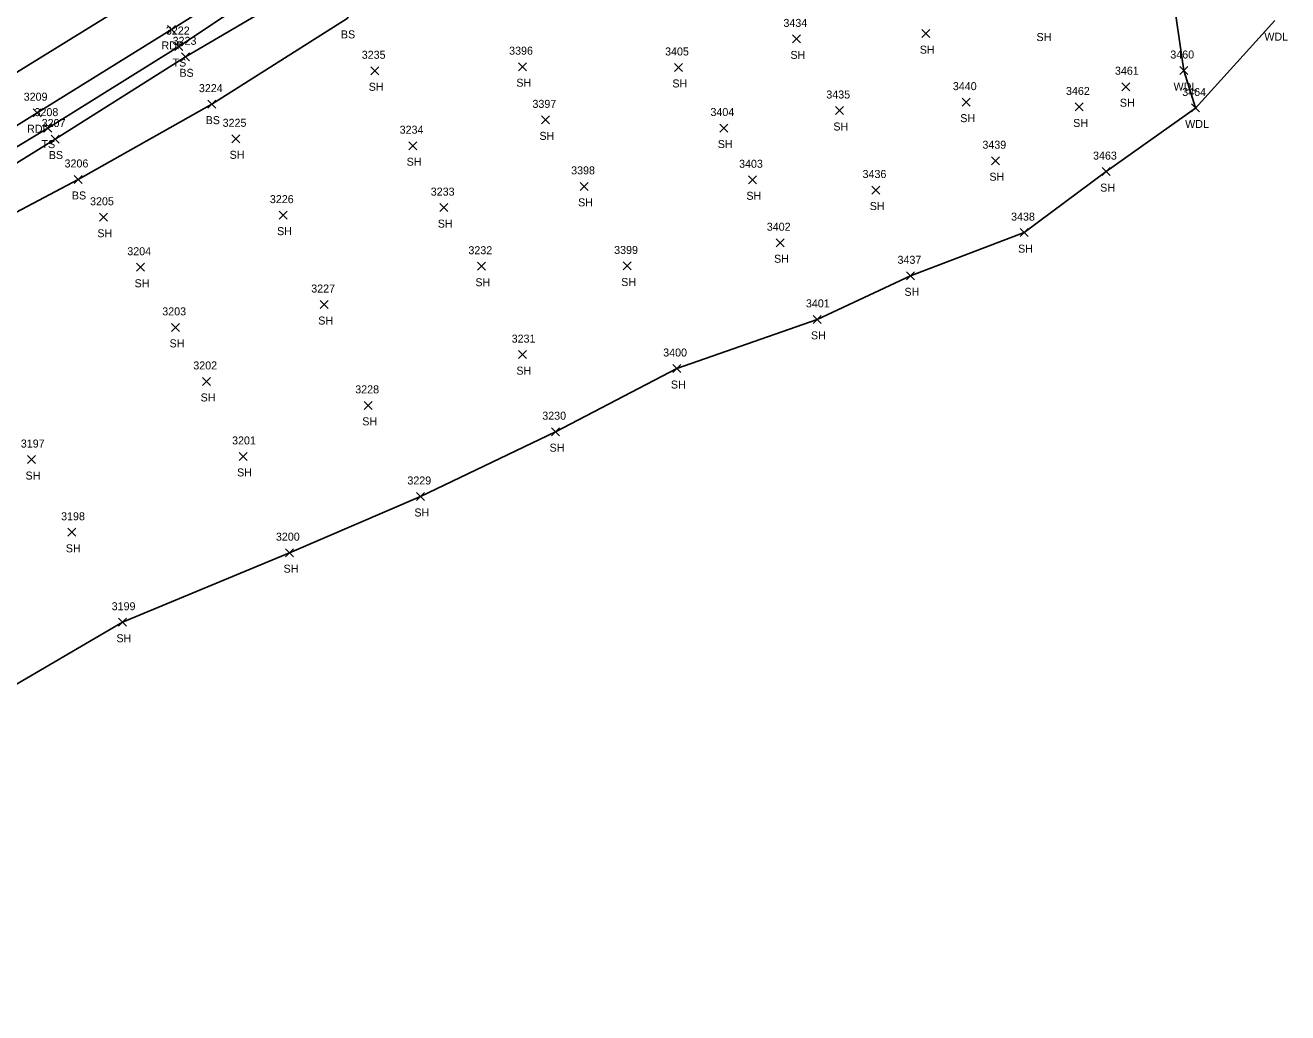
# Model space of a CAD drawing. Extents: x 1443590 to 1445966, y 578314 to 580556.
# Drawn here: x 1443948 to 1444263.5, y 578545.9 to 578792.7 of the extents above; entities that cross this region are included whole.
import ezdxf

# ---------------------------------------------------------------- set-up
doc = ezdxf.new("R2010")
doc.units = 0
for name, color, linetype in [('L_A', 7, 'Continuous'), ('L_I', 7, 'Continuous'), ('L_TIC', 7, 'Continuous'), ('LAWA', 7, 'Continuous'), ('LELB', 7, 'Continuous'), ('LSOGP', 7, 'Continuous'), ('P_A', 7, 'Continuous'), ('P_I', 7, 'Continuous'), ('P_TIC', 7, 'Continuous'), ('PET', 7, 'Continuous'), ('PRC', 7, 'Continuous')]:
    doc.layers.add(name, color=color, linetype=linetype)

msp = doc.modelspace()

# ---------------------------------------------------------------- linework, layer by layer
at = {"layer": 'L_TIC'}
for points in [[(1444139.75, 578788.3), (1444141.75, 578790.3)], [(1444141.75, 578788.3), (1444139.75, 578790.3)], [(1444172.09, 578789.62), (1444174.09, 578791.62)], [(1444174.09, 578789.62), (1444172.09, 578791.62)], [(1443985.4, 578786.39), (1443987.4, 578788.39)], [(1443987.4, 578786.39), (1443985.4, 578788.39)], [(1443987.08, 578783.83), (1443989.08, 578785.83)], [(1443989.08, 578783.83), (1443987.08, 578785.83)], [(1444071.24, 578781.36), (1444073.24, 578783.36)], [(1444073.24, 578781.36), (1444071.24, 578783.36)], [(1444110.25, 578781.17), (1444112.25, 578783.17)], [(1444112.25, 578781.17), (1444110.25, 578783.17)], [(1444034.35, 578780.34), (1444036.35, 578782.34)], [(1444036.35, 578780.34), (1444034.35, 578782.34)], [(1444236.58, 578780.4), (1444238.58, 578782.4)], [(1444238.58, 578780.4), (1444236.58, 578782.4)], [(1444222.09, 578776.35), (1444224.09, 578778.35)], [(1444224.09, 578776.35), (1444222.09, 578778.35)], [(1443993.65, 578772), (1443995.65, 578774)], [(1443995.65, 578772), (1443993.65, 578774)], [(1444182.19, 578772.5), (1444184.19, 578774.5)], [(1444184.19, 578772.5), (1444182.19, 578774.5)], [(1444210.42, 578771.3), (1444212.42, 578773.3)], [(1444212.42, 578771.3), (1444210.42, 578773.3)], [(1444077.02, 578768.07), (1444079.02, 578770.07)], [(1444079.02, 578768.07), (1444077.02, 578770.07)], [(1444150.47, 578770.41), (1444152.47, 578772.41)], [(1444152.47, 578770.41), (1444150.47, 578772.41)], [(1444239.48, 578771.04), (1444241.48, 578773.04)], [(1444241.48, 578771.04), (1444239.48, 578773.04)], [(1443952.64, 578766.01), (1443954.64, 578768.01)], [(1443954.64, 578766.01), (1443952.64, 578768.01)], [(1444121.59, 578766.03), (1444123.59, 578768.03)], [(1444123.59, 578766.03), (1444121.59, 578768.03)], [(1443954.43, 578763.28), (1443956.43, 578765.28)], [(1443956.43, 578763.28), (1443954.43, 578765.28)], [(1443999.58, 578763.34), (1444001.58, 578765.34)], [(1444001.58, 578763.34), (1443999.58, 578765.34)], [(1444043.83, 578761.61), (1444045.83, 578763.61)], [(1444045.83, 578761.61), (1444043.83, 578763.61)], [(1444189.49, 578757.86), (1444191.49, 578759.86)], [(1444191.49, 578757.86), (1444189.49, 578759.86)], [(1443960.2, 578753.18), (1443962.2, 578755.18)], [(1443962.2, 578753.18), (1443960.2, 578755.18)], [(1444128.74, 578753.1), (1444130.74, 578755.1)], [(1444130.74, 578753.1), (1444128.74, 578755.1)], [(1444217.18, 578755.14), (1444219.18, 578757.14)], [(1444219.18, 578755.14), (1444217.18, 578757.14)], [(1444086.69, 578751.45), (1444088.69, 578753.45)], [(1444088.69, 578751.45), (1444086.69, 578753.45)], [(1444159.59, 578750.54), (1444161.59, 578752.54)], [(1444161.59, 578750.54), (1444159.59, 578752.54)], [(1444051.6, 578746.14), (1444053.6, 578748.14)], [(1444053.6, 578746.14), (1444051.6, 578748.14)], [(1443966.52, 578743.73), (1443968.52, 578745.73)], [(1443968.52, 578743.73), (1443966.52, 578745.73)], [(1444011.44, 578744.26), (1444013.44, 578746.26)], [(1444013.44, 578744.26), (1444011.44, 578746.26)], [(1444196.65, 578739.89), (1444198.65, 578741.89)], [(1444198.65, 578739.89), (1444196.65, 578741.89)], [(1444135.67, 578737.36), (1444137.67, 578739.36)], [(1444137.67, 578737.36), (1444135.67, 578739.36)], [(1443975.83, 578731.24), (1443977.83, 578733.24)], [(1443977.83, 578731.24), (1443975.83, 578733.24)], [(1444061.01, 578731.49), (1444063.01, 578733.49)], [(1444063.01, 578731.49), (1444061.01, 578733.49)], [(1444097.45, 578731.56), (1444099.45, 578733.56)], [(1444099.45, 578731.56), (1444097.45, 578733.56)], [(1444168.26, 578729.1), (1444170.26, 578731.1)], [(1444170.26, 578729.1), (1444168.26, 578731.1)], [(1444021.73, 578721.92), (1444023.73, 578723.92)], [(1444023.73, 578721.92), (1444021.73, 578723.92)], [(1444144.89, 578718.21), (1444146.89, 578720.21)], [(1444146.89, 578718.21), (1444144.89, 578720.21)], [(1443984.57, 578716.21), (1443986.57, 578718.21)], [(1443986.57, 578716.21), (1443984.57, 578718.21)], [(1444071.25, 578709.4), (1444073.25, 578711.4)], [(1444073.25, 578709.4), (1444071.25, 578711.4)], [(1444109.87, 578705.93), (1444111.87, 578707.93)], [(1444111.87, 578705.93), (1444109.87, 578707.93)], [(1443992.33, 578702.7), (1443994.33, 578704.7)], [(1443994.33, 578702.7), (1443992.33, 578704.7)], [(1444032.73, 578696.72), (1444034.73, 578698.72)], [(1444034.73, 578696.72), (1444032.73, 578698.72)], [(1444079.56, 578690.14), (1444081.56, 578692.14)], [(1444081.56, 578690.14), (1444079.56, 578692.14)], [(1443948.58, 578683.18), (1443950.58, 578685.18)], [(1443950.58, 578683.18), (1443948.58, 578685.18)], [(1444001.46, 578683.96), (1444003.46, 578685.96)], [(1444003.46, 578683.96), (1444001.46, 578685.96)], [(1444045.76, 578673.95), (1444047.76, 578675.95)], [(1444047.76, 578673.95), (1444045.76, 578675.95)], [(1443958.64, 578665), (1443960.64, 578667)], [(1443960.64, 578665), (1443958.64, 578667)], [(1444013.06, 578659.91), (1444015.06, 578661.91)], [(1444015.06, 578659.91), (1444013.06, 578661.91)], [(1443971.29, 578642.52), (1443973.29, 578644.52)], [(1443973.29, 578642.52), (1443971.29, 578644.52)]]:
    msp.add_lwpolyline(points, dxfattribs=at)
at = {"layer": 'LAWA'}
msp.add_lwpolyline([(1444048.1, 578821.32), (1444049.15, 578815.65), (1444053.76, 578808.6), (1444089.15, 578821), (1444115.87, 578831.04), (1444149.45, 578834.28), (1444175.65, 578843.43), (1444202.18, 578846.34), (1444218.5, 578835.02), (1444228, 578822.21), (1444234.72, 578800.9), (1444237.58, 578781.4), (1444240.48, 578772.04)], dxfattribs=at)
at = {"layer": 'LELB'}
for points in [[(1443615.53, 578549.09), (1443647.15, 578571.87), (1443656.71, 578577.24), (1443699.78, 578605.86), (1443739.16, 578631.36), (1443774.01, 578653.63), (1443806.33, 578675.43), (1443846.66, 578699.7), (1443880.84, 578720.78), (1443915.45, 578744.08), (1443953.64, 578767.01), (1443986.4, 578787.39), (1444018.89, 578809.07), (1444030.21, 578814.65), (1444042.78, 578823.31), (1444045.84, 578825.91), (1444071.11, 578843.04), (1444083.63, 578848.63), (1444101.33, 578858.93), (1444132.81, 578873.64), (1444159.48, 578890.92), (1444189.04, 578910.16), (1444210.73, 578922.71), (1444214.87, 578926.32)], [(1443617.38, 578545.93), (1443649.59, 578568.34), (1443659.37, 578572.13), (1443703.15, 578599.79), (1443742.08, 578627.42), (1443775.99, 578650.05), (1443809.17, 578670.17), (1443847.87, 578696.41), (1443882.88, 578718.02), (1443917, 578740.41), (1443955.43, 578764.28), (1443988.08, 578784.83), (1444022, 578804.82), (1444030.48, 578811.54), (1444041.56, 578818.92), (1444047.79, 578822.82), (1444063.67, 578832.31)], [(1443707.24, 578593.68), (1443747.78, 578617.37), (1443781.43, 578641.01), (1443814.18, 578660.08), (1443852.96, 578688.17), (1443888.41, 578709.13), (1443921.62, 578733.3), (1443961.2, 578754.18), (1443994.65, 578773), (1444028.44, 578794.43), (1444032.53, 578801.75)]]:
    msp.add_lwpolyline(points, dxfattribs=at)
at = {"layer": 'LSOGP'}
msp.add_lwpolyline([(1443938.08, 578623.58), (1443972.29, 578643.52), (1444014.06, 578660.91), (1444046.77, 578674.95), (1444080.55, 578691.14), (1444110.87, 578706.93), (1444145.89, 578719.21), (1444169.26, 578730.1), (1444197.66, 578740.89), (1444218.18, 578756.14), (1444240.48, 578772.03), (1444260.27, 578793.87)], dxfattribs=at)
at = {"layer": 'P_TIC'}
for points in [[(1443983.55, 578790.67), (1443985.55, 578792.67)], [(1443985.55, 578790.67), (1443983.55, 578792.67)], [(1443949.95, 578769.86), (1443951.95, 578771.86)], [(1443951.95, 578769.86), (1443949.95, 578771.86)]]:
    msp.add_lwpolyline(points, dxfattribs=at)
at = {"layer": 'PET'}
msp.add_lwpolyline([(1443612.4, 578554.37), (1443645.04, 578575.45), (1443657.24, 578583.2), (1443697.44, 578609.18), (1443737.28, 578634.55), (1443772.29, 578657.29), (1443804.75, 578678.07), (1443844.06, 578703.73), (1443878.04, 578725.08), (1443913.76, 578747.61), (1443950.95, 578770.86), (1443984.55, 578791.67), (1444017.37, 578812.19), (1444029.71, 578820.04), (1444042.88, 578828.09), (1444081.78, 578851.73), (1444099.65, 578862.29), (1444128.94, 578879.48), (1444156.82, 578896.17), (1444186.94, 578914.09), (1444214.07, 578930.35)], dxfattribs=at)
at = {"layer": 'PRC'}
msp.add_lwpolyline([(1443607.19, 578563.71), (1443645.74, 578588.68), (1443691.8, 578618.64), (1443730.92, 578643.94), (1443766.58, 578667.23), (1443799.08, 578688.06), (1443838.06, 578712.83), (1443872.72, 578734.91), (1443908.54, 578757.41), (1443944.72, 578780.26), (1443979.55, 578801.84), (1444011.31, 578821.61), (1444031.47, 578833.87), (1444076.05, 578860.79), (1444093.92, 578871.67), (1444123.23, 578888.92), (1444152.19, 578905.95), (1444180.96, 578922.73), (1444208.88, 578939.04)], dxfattribs=at)

# ---------------------------------------------------------------- texts
at = {"layer": 'L_A'}
for s, p in [('BS', (1444026.88, 578789.43)), ('SH', (1444200.75, 578788.76)), ('WDL', (1444257.69, 578788.87)), ('SH', (1444139.24, 578784.3)), ('SH', (1444171.57, 578785.62)), ('TS', (1443984.81, 578782.39)), ('BS', (1443986.52, 578779.83)), ('SH', (1444033.84, 578776.34)), ('SH', (1444070.73, 578777.36)), ('SH', (1444109.73, 578777.17)), ('WDL', (1444235, 578776.4)), ('SH', (1444221.58, 578772.35)), ('BS', (1443993.09, 578768)), ('SH', (1444181.68, 578768.5)), ('SH', (1444149.96, 578766.41)), ('SH', (1444209.91, 578767.3)), ('WDL', (1444237.9, 578767.04)), ('TS', (1443952.05, 578762.01)), ('SH', (1444076.51, 578764.07)), ('SH', (1444121.08, 578762.03)), ('BS', (1443953.87, 578759.28)), ('SH', (1443999.07, 578759.34)), ('SH', (1444043.31, 578757.61)), ('SH', (1444188.98, 578753.86)), ('BS', (1443959.64, 578749.18)), ('SH', (1444128.23, 578749.1)), ('SH', (1444216.66, 578751.14)), ('SH', (1444086.18, 578747.45)), ('SH', (1444159.07, 578746.54)), ('SH', (1443966.01, 578739.73)), ('SH', (1444010.93, 578740.26)), ('SH', (1444051.09, 578742.14)), ('SH', (1444135.16, 578733.36)), ('SH', (1444196.14, 578735.89)), ('SH', (1443975.32, 578727.24)), ('SH', (1444060.5, 578727.49)), ('SH', (1444096.94, 578727.56)), ('SH', (1444167.75, 578725.1)), ('SH', (1444021.22, 578717.92)), ('SH', (1443984.06, 578712.21)), ('SH', (1444144.37, 578714.21)), ('SH', (1444070.74, 578705.4)), ('SH', (1444109.36, 578701.93)), ('SH', (1443991.81, 578698.7)), ('SH', (1444032.22, 578692.72)), ('SH', (1444079.04, 578686.14)), ('SH', (1444000.94, 578679.96)), ('SH', (1443948.06, 578679.18)), ('SH', (1444045.25, 578669.95)), ('SH', (1443958.13, 578661)), ('SH', (1444012.55, 578655.91)), ('SH', (1443970.78, 578638.52))]:
    msp.add_text(s, height=2, dxfattribs=at).set_placement(p)
at = {"layer": 'L_I'}
for s, p in [('3222', (1443983.14, 578790.39)), ('3434', (1444137.49, 578792.3)), ('3223', (1443984.82, 578787.83)), ('3235', (1444032.09, 578784.34)), ('3396', (1444068.93, 578785.36)), ('3405', (1444107.91, 578785.17)), ('3460', (1444234.19, 578784.4)), ('3461', (1444220.35, 578780.35)), ('3224', (1443991.39, 578776)), ('3435', (1444148.21, 578774.41)), ('3440', (1444179.84, 578776.5)), ('3462', (1444208.11, 578775.3)), ('3464', (1444237.17, 578775.04)), ('3397', (1444074.76, 578772.07)), ('3208', (1443950.3, 578770.01)), ('3404', (1444119.25, 578770.03)), ('3207', (1443952.09, 578767.28)), ('3225', (1443997.32, 578767.34)), ('3234', (1444041.57, 578765.61)), ('3439', (1444187.22, 578761.86)), ('3463', (1444214.87, 578759.14)), ('3206', (1443957.81, 578757.18)), ('3398', (1444084.43, 578755.45)), ('3403', (1444126.4, 578757.1)), ('3436', (1444157.27, 578754.54)), ('3233', (1444049.34, 578750.14)), ('3205', (1443964.19, 578747.73)), ('3226', (1444009.13, 578748.26)), ('3438', (1444194.39, 578743.89)), ('3402', (1444133.33, 578741.36)), ('3204', (1443973.49, 578735.24)), ('3232', (1444058.75, 578735.49)), ('3399', (1444095.18, 578735.56)), ('3437', (1444166, 578733.1)), ('3227', (1444019.47, 578725.92)), ('3401', (1444143.11, 578722.21)), ('3203', (1443982.23, 578720.21)), ('3231', (1444069.56, 578713.4)), ('3400', (1444107.44, 578709.93)), ('3202', (1443989.99, 578706.7)), ('3228', (1444030.47, 578700.72)), ('3230', (1444077.21, 578694.14)), ('3197', (1443946.88, 578687.18)), ('3201', (1443999.68, 578687.96)), ('3229', (1444043.5, 578677.95)), ('3198', (1443956.95, 578669)), ('3200', (1444010.64, 578663.91)), ('3199', (1443969.59, 578646.52))]:
    msp.add_text(s, height=2, dxfattribs=at).set_placement(p)
at = {"layer": 'P_A'}
for p in [(1443982.04, 578786.67), (1443948.44, 578765.86)]:
    msp.add_text('RDP', height=2, dxfattribs=at).set_placement(p)
at = {"layer": 'P_I'}
msp.add_text('3209', height=2, dxfattribs=at).set_placement((1443947.6, 578773.86))

doc.saveas('drawing.dxf')
